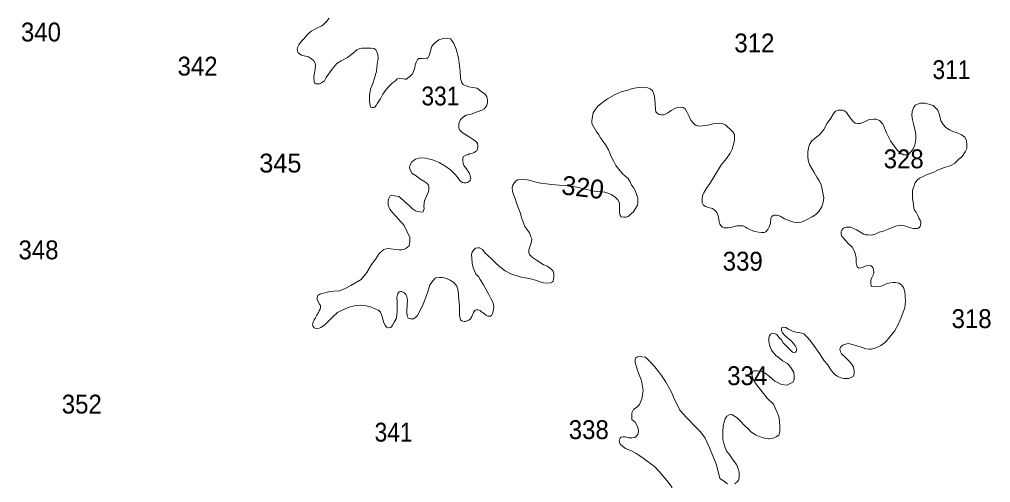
# Model space of a CAD drawing. Extents: x 445.4 to 500, y 8728.7 to 8784.
# Drawn here: x 464.83 to 473.06, y 8742.64 to 8746.56 of the extents above; entities that cross this region are included whole.
import ezdxf
from ezdxf.enums import TextEntityAlignment as Align

# ---------------------------------------------------------------- set-up
doc = ezdxf.new("R2010")
doc.units = 0
doc.header["$LTSCALE"] = 0.064
doc.layers.add('2', color=7, linetype='Continuous', lineweight=13)
doc.layers.add('21', color=7, linetype='Continuous')
doc.layers.add('61', color=7, linetype='Continuous')

msp = doc.modelspace()

# ---------------------------------------------------------------- linework, layer by layer
at = {"layer": '2'}
for points in [[(468.1156, 8746.0588), (468.1018, 8746.0576), (468.0867, 8746.0614), (468.0754, 8746.0626), (468.0565, 8746.0651), (468.0452, 8746.0639), (468.0326, 8746.0576), (468.0213, 8746.045), (468.0049, 8746.0312), (467.9898, 8746.0212), (467.9648, 8745.9948), (467.9419, 8745.969), (467.9145, 8745.9294), (467.8946, 8745.8898), (467.8702, 8745.8547), (467.858, 8745.8349), (467.8458, 8745.8212), (467.8351, 8745.8182), (467.8229, 8745.8167), (467.8107, 8745.8212), (467.8061, 8745.8365), (467.8, 8745.8684), (467.8, 8745.9202), (467.8107, 8745.972), (467.829, 8746.0207), (467.8443, 8746.0664), (467.8595, 8746.1258), (467.8672, 8746.1837), (467.8748, 8746.2309), (467.8717, 8746.27), (467.8611, 8746.2943), (467.8534, 8746.3065), (467.8397, 8746.3172), (467.8138, 8746.3202), (467.7726, 8746.3204), (467.7355, 8746.3204), (467.7191, 8746.3174), (467.6939, 8746.307), (467.6627, 8746.2774), (467.6137, 8746.2403), (467.5617, 8746.2136), (467.523, 8746.1899), (467.4963, 8746.1573), (467.4606, 8746.1083), (467.4334, 8746.0709), (467.4186, 8746.0442), (467.3948, 8746.0264), (467.377, 8746.019), (467.3636, 8746.0175), (467.3458, 8746.0175), (467.3383, 8746.0234), (467.3324, 8746.0383), (467.3309, 8746.0501), (467.3279, 8746.062), (467.3279, 8746.0813), (467.3309, 8746.0946), (467.3383, 8746.1243), (467.3443, 8746.1688), (467.3398, 8746.1925), (467.3279, 8746.2132), (467.3101, 8746.231), (467.2849, 8746.2473), (467.2477, 8746.2562), (467.2254, 8746.2614), (467.2105, 8746.2703), (467.1972, 8746.2821), (467.1927, 8746.2895), (467.1882, 8746.3088), (467.1912, 8746.3266), (467.2031, 8746.3503), (467.2254, 8746.38), (467.2462, 8746.4022), (467.2729, 8746.4334), (467.3056, 8746.466), (467.3353, 8746.4778), (467.3591, 8746.4927), (467.3962, 8746.5105), (467.4141, 8746.5238), (467.4363, 8746.5461), (467.4586, 8746.5742)], [(468.1609, 8745.358), (468.1902, 8745.3794), (468.2311, 8745.3909), (468.2766, 8745.3892), (468.3344, 8745.3752), (468.3904, 8745.3525), (468.4393, 8745.3228), (468.4883, 8745.2879), (468.5303, 8745.2477), (468.5706, 8745.1953), (468.5898, 8745.1814), (468.6003, 8745.1796), (468.6161, 8745.1796), (468.6318, 8745.1831), (468.6493, 8745.1936), (468.6581, 8745.2041), (468.6598, 8745.2163), (468.6581, 8745.2303), (468.6476, 8745.2582), (468.6231, 8745.2984), (468.6003, 8745.3246), (468.5951, 8745.3438), (468.5916, 8745.3665), (468.5916, 8745.3892), (468.5986, 8745.4014), (468.6178, 8745.4136), (468.6353, 8745.4171), (468.6493, 8745.4241), (468.6738, 8745.4294), (468.6878, 8745.4363), (468.7001, 8745.4433), (468.7106, 8745.4503), (468.7193, 8745.4783), (468.7193, 8745.4957), (468.7158, 8745.5114), (468.7106, 8745.5219), (468.7001, 8745.5324), (468.6791, 8745.5464), (468.6458, 8745.5691), (468.6038, 8745.5953), (468.5793, 8745.611), (468.5656, 8745.6245), (468.5586, 8745.6454), (468.5569, 8745.6803), (468.5709, 8745.7153), (468.5971, 8745.738), (468.6216, 8745.7537), (468.6636, 8745.7607), (468.7144, 8745.7799), (468.7529, 8745.7956), (468.7739, 8745.8078), (468.7879, 8745.8236), (468.7949, 8745.8375), (468.8019, 8745.8585), (468.8019, 8745.8864), (468.7966, 8745.9091), (468.7774, 8745.9336), (468.7476, 8745.9545), (468.7126, 8745.9807), (468.6734, 8745.9862), (468.6437, 8745.9941), (468.6199, 8746.002), (468.5942, 8746.0139), (468.5843, 8746.0277), (468.5724, 8746.0652), (468.5685, 8746.1265), (468.5566, 8746.2391), (468.5368, 8746.3121), (468.517, 8746.3596), (468.4972, 8746.3892), (468.4873, 8746.3991), (468.4656, 8746.403), (468.4458, 8746.405), (468.4161, 8746.401), (468.3884, 8746.3912), (468.3666, 8746.3754), (468.3429, 8746.3536), (468.3251, 8746.3319), (468.3211, 8746.3062), (468.3072, 8746.2588), (468.2971, 8746.2424), (468.2903, 8746.2356), (468.282, 8746.2326), (468.2721, 8746.231), (468.2471, 8746.2318), (468.2326, 8746.2333), (468.2198, 8746.2318), (468.2076, 8746.2257), (468.2008, 8746.2129), (468.1955, 8746.2015), (468.1932, 8746.1932), (468.1886, 8746.1803), (468.1871, 8746.1697), (468.1848, 8746.1606), (468.1826, 8746.1462), (468.1788, 8746.1364), (468.175, 8746.1235), (468.1659, 8746.1031), (468.1431, 8746.0803), (468.1244, 8746.0651), (468.1156, 8746.0588)], [(471.3985, 8744.8459), (471.3636, 8744.857), (471.3191, 8744.8744), (471.2826, 8744.8966), (471.2683, 8744.9029), (471.2524, 8744.9045), (471.2302, 8744.9061), (471.2207, 8744.9029), (471.2111, 8744.895), (471.2016, 8744.8776), (471.1984, 8744.8379), (471.1889, 8744.8047), (471.1778, 8744.784), (471.1587, 8744.765), (471.1444, 8744.7587), (471.1254, 8744.7587), (471.1016, 8744.7619), (471.0635, 8744.7666), (471.0253, 8744.7825), (471.0031, 8744.7936), (470.9872, 8744.8031), (470.965, 8744.8142), (470.9459, 8744.8157), (470.9142, 8744.8142), (470.8824, 8744.8062), (470.8602, 8744.8015), (470.8411, 8744.7983), (470.8221, 8744.7983), (470.8078, 8744.7983), (470.7919, 8744.8031), (470.7824, 8744.8157), (470.7697, 8744.8284), (470.7633, 8744.8506), (470.7554, 8744.8982), (470.7458, 8744.9267), (470.7331, 8744.9425), (470.7077, 8744.9616), (470.6712, 8744.9711), (470.6482, 8744.9779), (470.6276, 8744.9921), (470.6196, 8745.0096), (470.6196, 8745.0397), (470.6228, 8745.0682), (470.6387, 8745.0999), (470.6641, 8745.1411), (470.6895, 8745.1776), (470.7292, 8745.2457), (470.7851, 8745.3339), (470.8263, 8745.3846), (470.8565, 8745.4305), (470.874, 8745.4654), (470.8851, 8745.5035), (470.8946, 8745.5399), (470.8946, 8745.57), (470.893, 8745.5875), (470.881, 8745.6125), (470.8583, 8745.6352), (470.8386, 8745.6518), (470.8174, 8745.67), (470.7901, 8745.682), (470.7598, 8745.6836), (470.7144, 8745.6805), (470.6584, 8745.6654), (470.622, 8745.6624), (470.5917, 8745.6594), (470.5705, 8745.6639), (470.5569, 8745.673), (470.5433, 8745.6866), (470.5251, 8745.7108), (470.5099, 8745.741), (470.4918, 8745.7803), (470.476, 8745.8077), (470.4593, 8745.8183), (470.4396, 8745.8213), (470.4108, 8745.8183), (470.3942, 8745.8108), (470.3578, 8745.7926), (470.3306, 8745.773), (470.3048, 8745.7594), (470.2927, 8745.7548), (470.2745, 8745.7548), (470.2548, 8745.7594), (470.2397, 8745.7684), (470.2276, 8745.782), (470.2246, 8745.8017), (470.2215, 8745.8501), (470.217, 8745.9105), (470.2077, 8745.9401), (470.1987, 8745.9582), (470.1805, 8745.9748), (470.1608, 8745.9839), (470.1335, 8745.9884), (470.0987, 8745.9899), (470.029, 8745.9779), (469.9912, 8745.9643), (469.9351, 8745.9491), (469.8821, 8745.9265), (469.817, 8745.8917), (469.7761, 8745.86), (469.7367, 8745.8297), (469.7186, 8745.8055)], [(472.422, 8745.1762), (472.4436, 8745.203), (472.4624, 8745.2191), (472.5001, 8745.2353), (472.527, 8745.2487), (472.562, 8745.2621), (472.5889, 8745.2729), (472.6105, 8745.2836), (472.6428, 8745.2971), (472.6831, 8745.3105), (472.7208, 8745.3239), (472.7612, 8745.3454), (472.7935, 8745.3776), (472.8231, 8745.4018), (472.85, 8745.4421), (472.8635, 8745.469), (472.8646, 8745.5009), (472.8599, 8745.5358), (472.8456, 8745.5659), (472.8186, 8745.5849), (472.782, 8745.6024), (472.7439, 8745.6151), (472.7153, 8745.6277), (472.6852, 8745.6468), (472.6661, 8745.6705), (472.6439, 8745.7054), (472.6312, 8745.7561), (472.6169, 8745.7942), (472.5991, 8745.8156), (472.5769, 8745.8347), (472.5499, 8745.8426), (472.5102, 8745.8537), (472.4721, 8745.8537), (472.4451, 8745.8473), (472.4244, 8745.8362), (472.4101, 8745.8156), (472.399, 8745.7839), (472.3974, 8745.7538), (472.4022, 8745.7142), (472.4149, 8745.6682), (472.426, 8745.6207), (472.4321, 8745.5881), (472.4321, 8745.5485), (472.4225, 8745.4994), (472.4098, 8745.4677), (472.3924, 8745.4439), (472.3701, 8745.4185), (472.3495, 8745.4154), (472.3272, 8745.417), (472.313, 8745.4249), (472.2764, 8745.4534), (472.2447, 8745.4946), (472.2177, 8745.5358), (472.1827, 8745.604), (472.151, 8745.6769), (472.124, 8745.707), (472.0954, 8745.7181), (472.0748, 8745.7197), (472.0366, 8745.7149), (471.9969, 8745.6959), (471.9588, 8745.6817), (471.9429, 8745.6817), (471.9159, 8745.6848), (471.8985, 8745.7007), (471.8747, 8745.7308), (471.8445, 8745.7752), (471.8264, 8745.7895), (471.8089, 8745.7958), (471.793, 8745.7958), (471.7756, 8745.7942), (471.7517, 8745.7863), (471.7311, 8745.7625), (471.7104, 8745.7277), (471.6803, 8745.6849), (471.6517, 8745.631), (471.6168, 8745.5898), (471.5771, 8745.5565), (471.5501, 8745.5359), (471.531, 8745.5042), (471.5215, 8745.4756), (471.5151, 8745.4392), (471.5151, 8745.4027), (471.5199, 8745.3726), (471.531, 8745.3353), (471.55, 8745.3005), (471.5707, 8745.2656), (471.5929, 8745.226), (471.6104, 8745.2006), (471.6247, 8745.1705), (471.6342, 8745.1404), (471.6437, 8745.0944), (471.6517, 8745.0524), (471.6469, 8745.0144), (471.6358, 8744.9748), (471.6104, 8744.9367), (471.5834, 8744.9114), (471.5516, 8744.8908), (471.504, 8744.8654), (471.4589, 8744.8459), (471.4287, 8744.8427), (471.3985, 8744.8459)], [(469.7186, 8745.8055), (469.6974, 8745.7723), (469.6898, 8745.742), (469.6847, 8745.7052), (469.6862, 8745.6825), (469.7014, 8745.6523), (469.7256, 8745.6115), (469.7423, 8745.5903), (469.7574, 8745.5616), (469.7756, 8745.5389), (469.8076, 8745.4928), (469.8258, 8745.4581), (469.8485, 8745.4037), (469.8713, 8745.3613), (469.8894, 8745.3266), (469.9243, 8745.282), (469.9485, 8745.2533), (469.9909, 8745.22), (470.0106, 8745.1883), (470.0227, 8745.158), (470.0379, 8745.1399), (470.05, 8745.1187), (470.0636, 8745.0825), (470.0742, 8745.0497), (470.0742, 8745.0296), (470.0742, 8745.0094), (470.0722, 8744.9893), (470.0561, 8744.9612), (470.0379, 8744.933), (470.0077, 8744.9088), (469.9936, 8744.8947), (469.9774, 8744.8867), (469.9653, 8744.8867), (469.9553, 8744.8887), (469.9351, 8744.8907), (469.925, 8744.9028), (469.921, 8744.9269), (469.919, 8744.9752), (469.9196, 8745.0108), (469.9052, 8745.0352), (469.8836, 8745.0567), (469.8535, 8745.0782), (469.8204, 8745.0911), (469.7945, 8745.0997), (469.7083, 8745.1097), (469.6249, 8745.1241), (469.5718, 8745.1384), (469.5258, 8745.147), (469.4626, 8745.1556), (469.4079, 8745.1585), (469.3476, 8745.1657), (469.2491, 8745.1772), (469.2017, 8745.1887), (469.1643, 8745.1988), (469.1385, 8745.2045), (469.1054, 8745.2088), (469.0781, 8745.2074), (469.058, 8745.2045), (469.0451, 8745.1959), (469.0293, 8745.1815), (469.0149, 8745.1586), (469.0106, 8745.1385), (469.012, 8745.107), (469.0221, 8745.0811), (469.035, 8745.0467), (469.0479, 8745.0065), (469.0609, 8744.9707), (469.0767, 8744.9262), (469.0853, 8744.8975), (469.0939, 8744.8688), (469.1083, 8744.8308), (469.1184, 8744.8078), (469.1356, 8744.7877), (469.1557, 8744.7561), (469.1685, 8744.7225), (469.1766, 8744.7049), (469.175, 8744.6777), (469.1637, 8744.6457), (469.1509, 8744.6104), (469.151, 8744.5871), (469.1574, 8744.5711), (469.183, 8744.5471), (469.2167, 8744.5231), (469.2728, 8744.4863), (469.3081, 8744.4735), (469.3354, 8744.4527), (469.3562, 8744.4303), (469.3627, 8744.4095), (469.3643, 8744.3822), (469.3611, 8744.3614), (469.3562, 8744.3454), (469.3514, 8744.339), (469.3354, 8744.331), (469.3065, 8744.3294), (469.2745, 8744.3326), (469.2472, 8744.3406), (469.2071, 8744.3534), (469.1654, 8744.3662), (469.1221, 8744.3742), (469.0852, 8744.3806), (468.9986, 8744.4079)], [(467.9062, 8744.0534), (467.8944, 8744.0836), (467.8759, 8744.1004), (467.8473, 8744.1121), (467.8103, 8744.1289), (467.7733, 8744.1356), (467.7296, 8744.1423), (467.6741, 8744.1373), (467.6253, 8744.1256), (467.5631, 8744.097), (467.5304, 8744.0799), (467.495, 8744.048), (467.4412, 8743.9959), (467.4194, 8743.9724), (467.3883, 8743.9516), (467.3754, 8743.9464), (467.356, 8743.9439), (467.3418, 8743.9464), (467.3315, 8743.949), (467.3225, 8743.9619), (467.3186, 8743.976), (467.3238, 8743.9979), (467.3315, 8744.0172), (467.3444, 8744.0352), (467.356, 8744.0571), (467.3689, 8744.079), (467.3754, 8744.0944), (467.3818, 8744.1086), (467.3844, 8744.1227), (467.3844, 8744.1394), (467.3779, 8744.1497), (467.365, 8744.1716), (467.3586, 8744.1909), (467.3562, 8744.2051), (467.3644, 8744.2232), (467.3793, 8744.2347), (467.3974, 8744.2413), (467.4222, 8744.2479), (467.4536, 8744.2545), (467.4982, 8744.2595), (467.5477, 8744.2644), (467.5956, 8744.2825), (467.6418, 8744.3089), (467.731, 8744.36), (467.7771, 8744.4203), (467.8186, 8744.4854), (467.8542, 8744.5357), (467.8839, 8744.5801), (467.9076, 8744.6038), (467.9224, 8744.6126), (467.9432, 8744.6186), (467.9639, 8744.6215), (467.9817, 8744.6186), (468.0173, 8744.6126), (468.0529, 8744.6097), (468.0736, 8744.6097), (468.0914, 8744.6126), (468.1092, 8744.6215), (468.1359, 8744.6452), (468.1418, 8744.6807), (468.1418, 8744.7162), (468.1181, 8744.7695), (468.0944, 8744.8168), (468.047, 8744.8701), (467.9965, 8744.9263), (467.9731, 8744.9554), (467.9594, 8744.9885), (467.9594, 8745.0255), (467.9652, 8745.0469), (467.975, 8745.0684), (467.9848, 8745.0722), (468.014, 8745.0684), (468.0492, 8745.0645), (468.0628, 8745.0528), (468.0979, 8745.0216), (468.1389, 8744.9827), (468.1662, 8744.9593), (468.1916, 8744.9418), (468.2072, 8744.9359), (468.2267, 8744.932), (468.2424, 8744.9301), (468.256, 8744.934), (468.2599, 8744.9437), (468.2638, 8744.9593), (468.2619, 8744.9846), (468.2677, 8745.0255), (468.2833, 8745.0664), (468.297, 8745.0976), (468.3028, 8745.117), (468.3048, 8745.1346), (468.3048, 8745.1443), (468.3009, 8745.1579), (468.2872, 8745.1755), (468.2619, 8745.193), (468.2267, 8745.2125), (468.1955, 8745.2378), (468.1623, 8745.2592), (468.1448, 8745.2884), (468.1409, 8745.3079), (468.1433, 8745.3268), (468.1609, 8745.358)], [(471.7881, 8743.7699), (471.7953, 8743.7879), (471.8115, 8743.8023), (471.8242, 8743.8077), (471.8458, 8743.8149), (471.8584, 8743.8167), (471.8819, 8743.8113), (471.9306, 8743.7969), (471.9757, 8743.7825), (472.0063, 8743.7717), (472.0352, 8743.7681), (472.0568, 8743.7681), (472.1001, 8743.7825), (472.1344, 8743.8005), (472.1741, 8743.8293), (472.2101, 8743.8725), (472.2498, 8743.9211), (472.2823, 8743.9769), (472.3075, 8744.0382), (472.3369, 8744.1205), (472.3442, 8744.1746), (472.3369, 8744.2556), (472.3261, 8744.2916), (472.3099, 8744.315), (472.2864, 8744.3276), (472.2594, 8744.3348), (472.2395, 8744.3348), (472.2143, 8744.3312), (472.1728, 8744.3204), (472.1385, 8744.3024), (472.0754, 8744.297), (472.0556, 8744.3006), (472.0484, 8744.3204), (472.0484, 8744.3546), (472.0592, 8744.3762), (472.0733, 8744.4043), (472.0751, 8744.4223), (472.0715, 8744.4457), (472.0661, 8744.4619), (472.0517, 8744.4745), (472.0355, 8744.4781), (472.0102, 8744.4745), (471.9795, 8744.4601), (471.9471, 8744.4565), (471.9326, 8744.4673), (471.9254, 8744.5015), (471.9254, 8744.5429), (471.9146, 8744.5915), (471.8912, 8744.6329), (471.8551, 8744.6689), (471.8226, 8744.7031), (471.8028, 8744.7265), (471.7984, 8744.7432), (471.7993, 8744.7667), (471.803, 8744.7784), (471.8111, 8744.7893), (471.8192, 8744.7947), (471.8292, 8744.7992), (471.841, 8744.8037), (471.8563, 8744.8046), (471.8771, 8744.8019), (471.9016, 8744.7929), (471.9296, 8744.7793), (471.9613, 8744.7595), (471.9767, 8744.7531), (471.9893, 8744.745), (472.0083, 8744.7387), (472.0282, 8744.7369), (472.0545, 8744.736), (472.0852, 8744.7432), (472.1214, 8744.7595), (472.1531, 8744.7685), (472.1965, 8744.7866), (472.2604, 8744.8121), (472.2875, 8744.8175), (472.3029, 8744.8193), (472.3183, 8744.8184), (472.3355, 8744.8157), (472.3481, 8744.8103), (472.387, 8744.7967), (472.4106, 8744.7913), (472.425, 8744.7913), (472.4413, 8744.7931), (472.4531, 8744.7958), (472.4603, 8744.8012), (472.4676, 8744.8094), (472.4712, 8744.8211), (472.4748, 8744.8346), (472.4739, 8744.8473), (472.4703, 8744.8581), (472.4576, 8744.8807), (472.4459, 8744.9069), (472.4341, 8744.9304), (472.4196, 8744.9484), (472.4151, 8744.9638), (472.4104, 8744.9946), (472.4041, 8745.0483), (472.4041, 8745.0894), (472.4041, 8745.1162), (472.4167, 8745.1547), (472.422, 8745.1762)], [(468.9986, 8744.4079), (468.9505, 8744.4335), (468.904, 8744.4703), (468.8687, 8744.5007), (468.8302, 8744.5407), (468.7805, 8744.5839), (468.7575, 8744.6143), (468.7319, 8744.6271), (468.719, 8744.6287), (468.6998, 8744.6239), (468.6854, 8744.6111), (468.6709, 8744.5919), (468.6661, 8744.5711), (468.6677, 8744.5391), (468.6709, 8744.4991), (468.6789, 8744.4591), (468.6902, 8744.4319), (468.703, 8744.4046), (468.7239, 8744.3854), (468.7399, 8744.3582), (468.7639, 8744.3214), (468.8137, 8744.2326), (468.8329, 8744.1926), (468.849, 8744.1606), (468.8538, 8744.1237), (468.849, 8744.0917), (468.8442, 8744.0725), (468.8352, 8744.0551), (468.8252, 8744.0501), (468.8184, 8744.0484), (468.8033, 8744.0501), (468.7865, 8744.0585), (468.7612, 8744.0786), (468.7512, 8744.0853), (468.7394, 8744.0954), (468.7276, 8744.1004), (468.7192, 8744.1021), (468.7074, 8744.1038), (468.6973, 8744.0988), (468.6822, 8744.0803), (468.6671, 8744.0451), (468.6553, 8744.0232), (468.6418, 8744.0148), (468.6351, 8744.0115), (468.625, 8744.0081), (468.6149, 8744.0048), (468.6032, 8744.0048), (468.5847, 8744.0098), (468.5712, 8744.0182), (468.5628, 8744.0585), (468.5628, 8744.1323), (468.5578, 8744.186), (468.5527, 8744.2649), (468.5409, 8744.3035), (468.5157, 8744.3354), (468.4854, 8744.3539), (468.4451, 8744.3707), (468.4182, 8744.3774), (468.393, 8744.3774), (468.3644, 8744.374), (468.3543, 8744.3673), (468.3324, 8744.3388), (468.3122, 8744.3136), (468.2937, 8744.2465), (468.2567, 8744.1491), (468.2265, 8744.0921), (468.208, 8744.0551), (468.1911, 8744.0367), (468.1726, 8744.0266), (468.1525, 8744.0249), (468.1382, 8744.0299), (468.1298, 8744.0332), (468.1214, 8744.05), (468.1181, 8744.0853), (468.1197, 8744.1491), (468.1231, 8744.1826), (468.1181, 8744.2145), (468.108, 8744.233), (468.0962, 8744.2464), (468.0844, 8744.2531), (468.0727, 8744.2565), (468.0659, 8744.2582), (468.0525, 8744.2548), (468.0424, 8744.2397), (468.034, 8744.2078), (468.0357, 8744.1692), (468.0357, 8744.1222), (468.0357, 8744.087), (468.034, 8744.0551), (468.0273, 8744.0265), (468.0104, 8743.998), (467.9953, 8743.9711), (467.9869, 8743.9594), (467.9785, 8743.9527), (467.965, 8743.9493), (467.9583, 8743.951), (467.9448, 8743.956), (467.9331, 8743.9711), (467.923, 8743.9913), (467.9146, 8744.0232), (467.9062, 8744.0534)], [(470.8956, 8743.2024), (470.9173, 8743.1862), (470.9498, 8743.1538), (470.9768, 8743.125), (471.0129, 8743.0908), (471.0327, 8743.0674), (471.0778, 8743.0404), (471.1193, 8743.0242), (471.1482, 8743.0134), (471.1824, 8743.0098), (471.1896, 8743.0098), (471.2221, 8743.0152), (471.2474, 8743.026), (471.269, 8743.0386), (471.278, 8743.0674), (471.278, 8743.1088), (471.2762, 8743.1592), (471.269, 8743.197), (471.2564, 8743.233), (471.2257, 8743.3032), (471.1718, 8743.3528), (471.1285, 8743.4087), (471.078, 8743.4735), (471.0528, 8743.5131), (471.042, 8743.5509), (471.0456, 8743.5689), (471.0528, 8743.5815), (471.0636, 8743.5851), (471.0853, 8743.5851), (471.1177, 8743.5815), (471.1556, 8743.5653), (471.1917, 8743.5365), (471.2368, 8743.4969), (471.2927, 8743.4681), (471.3414, 8743.4645), (471.3666, 8743.4789), (471.3883, 8743.4897), (471.3991, 8743.5095), (471.3991, 8743.5437), (471.3973, 8743.5707), (471.372, 8743.6139), (471.3436, 8743.6475), (471.3004, 8743.6691), (471.2715, 8743.6943), (471.2444, 8743.7159), (471.2084, 8743.7609), (471.1903, 8743.8041), (471.1867, 8743.8365), (471.1849, 8743.8653), (471.1903, 8743.8834), (471.1993, 8743.896), (471.2156, 8743.905), (471.2318, 8743.9032), (471.2535, 8743.8924), (471.2769, 8743.8635), (471.2931, 8743.8473), (471.3076, 8743.8239), (471.3364, 8743.7933), (471.3707, 8743.7591), (471.3851, 8743.7447), (471.4014, 8743.7411), (471.4122, 8743.7447), (471.4212, 8743.7537), (471.423, 8743.7717), (471.4122, 8743.7951), (471.3941, 8743.8167), (471.3743, 8743.8401), (471.3202, 8743.8852), (471.3004, 8743.9068), (471.2913, 8743.9266), (471.2913, 8743.941), (471.2967, 8743.9518), (471.3094, 8743.9554), (471.3292, 8743.9518), (471.3509, 8743.9374), (471.3797, 8743.9248), (471.414, 8743.914), (471.4465, 8743.9104), (471.4807, 8743.8978), (471.5078, 8743.8726), (471.5366, 8743.8437), (471.5673, 8743.7987), (471.6142, 8743.7321), (471.6539, 8743.6709), (471.6845, 8743.6349), (471.7116, 8743.5935), (471.7387, 8743.5611), (471.7639, 8743.5413), (471.7946, 8743.5251), (471.8216, 8743.5197), (471.8631, 8743.5215), (471.901, 8743.5377), (471.9089, 8743.5575), (471.9089, 8743.5863), (471.9017, 8743.6151), (471.8855, 8743.6457), (471.862, 8743.6709), (471.8296, 8743.7051), (471.8025, 8743.7285), (471.7935, 8743.7465), (471.7881, 8743.7699)], [(470.3659, 8742.5969), (470.3202, 8742.6547), (470.2563, 8742.7321), (470.2152, 8742.7732), (470.1549, 8742.8201), (470.1162, 8742.8487), (470.0875, 8742.8688), (470.0589, 8742.8873), (470.0219, 8742.9058), (469.9916, 8742.9192), (469.9714, 8742.9276), (469.9597, 8742.9343), (469.9445, 8742.9461), (469.926, 8742.9629), (469.9193, 8742.9814), (469.9176, 8742.9981), (469.9243, 8743.0149), (469.9344, 8743.0233), (469.9496, 8743.0267), (469.9681, 8743.025), (469.9967, 8743.0183), (470.0236, 8743.0166), (470.0472, 8743.02), (470.0623, 8743.0284), (470.0774, 8743.0502), (470.0808, 8743.0754), (470.0758, 8743.1073), (470.0522, 8743.1493), (470.0253, 8743.1728), (470.0229, 8743.2017), (470.0229, 8743.2306), (470.0389, 8743.2563), (470.0678, 8743.2787), (470.0903, 8743.3011), (470.1096, 8743.3492), (470.1192, 8743.4198), (470.1064, 8743.5031), (470.0871, 8743.5512), (470.0711, 8743.5897), (470.0614, 8743.6282), (470.0539, 8743.6559), (470.0523, 8743.6804), (470.0588, 8743.6966), (470.067, 8743.7015), (470.0849, 8743.7064), (470.1094, 8743.7032), (470.1388, 8743.6999), (470.1616, 8743.6787), (470.1894, 8743.6543), (470.2204, 8743.6185), (470.2514, 8743.581), (470.2759, 8743.5468), (470.3085, 8743.4947), (470.3346, 8743.4507), (470.3607, 8743.4051), (470.3787, 8743.3611), (470.4297, 8743.2516), (470.4876, 8743.1902), (470.5636, 8743.1107), (470.6071, 8743.0674), (470.6469, 8743.0132), (470.6867, 8742.9265), (470.741, 8742.7893), (470.7699, 8742.6737), (470.8025, 8742.652), (470.8351, 8742.6267)], [(470.8974, 8742.6283), (470.916, 8742.644), (470.9303, 8742.6626), (470.9346, 8742.6869), (470.9332, 8742.727), (470.9246, 8742.7556), (470.9103, 8742.7899), (470.883, 8742.8286), (470.8486, 8742.8787), (470.83, 8742.9016), (470.8185, 8742.9259), (470.8027, 8742.9703), (470.7956, 8743.0032), (470.7946, 8743.062), (470.7982, 8743.1214), (470.8145, 8743.179), (470.8289, 8743.2006), (470.8487, 8743.2132), (470.8704, 8743.215), (470.8956, 8743.2024)]]:
    msp.add_lwpolyline(points, dxfattribs=at)

# ---------------------------------------------------------------- texts
at = {"layer": '21'}
for s, width, p in [('340', 0.95, (464.847, 8746.3775)), ('312', 0.95, (470.8933, 8746.2851)), ('342', 0.95, (466.1744, 8746.0884)), ('311', 0.9, (472.5723, 8746.0585)), ('331', 0.9, (468.2411, 8745.8353)), ('328', 0.95, (472.1588, 8745.3024)), ('348', 0.95, (464.8264, 8744.5308)), ('339', 0.95, (470.7946, 8744.4347)), ('318', 0.95, (472.7343, 8743.9478)), ('334', 0.95, (470.8327, 8743.4643)), ('352', 0.95, (465.193, 8743.2232)), ('341', 0.9, (467.8441, 8742.9854)), ('338', 0.95, (469.4899, 8743.0068))]:
    msp.add_text(s, height=0.16, dxfattribs=dict(at, width=width)).set_placement(p)
msp.add_text('345', height=0.16, dxfattribs=at).set_placement((466.8669, 8745.2664))
at = {"layer": '61'}
msp.add_text('320', height=0.16, rotation=353.149, dxfattribs=at).set_placement((469.5999, 8745.0614), align=Align.CENTER)

doc.saveas('drawing.dxf')
